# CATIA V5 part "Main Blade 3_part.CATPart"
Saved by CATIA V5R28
Part number: Main Blade 3_part
Definition: design
Nomenclature: Main Blade 3_part
Source: Unknown
Bounding box of the stored display mesh (mm): x 0.321 to 8.91, y -4.878 to 4.748, z 1.529 to 7.748
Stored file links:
  D:\paraturbo-cad\STEP\Turbocompressor_for_Christophe\Main Blade 3_part.CATPart
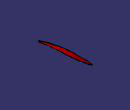
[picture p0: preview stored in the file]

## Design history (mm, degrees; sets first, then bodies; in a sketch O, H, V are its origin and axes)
Body1 "MANIFOLD_SOLID_BREP #37370" (main body)
  Solid1: solid without history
